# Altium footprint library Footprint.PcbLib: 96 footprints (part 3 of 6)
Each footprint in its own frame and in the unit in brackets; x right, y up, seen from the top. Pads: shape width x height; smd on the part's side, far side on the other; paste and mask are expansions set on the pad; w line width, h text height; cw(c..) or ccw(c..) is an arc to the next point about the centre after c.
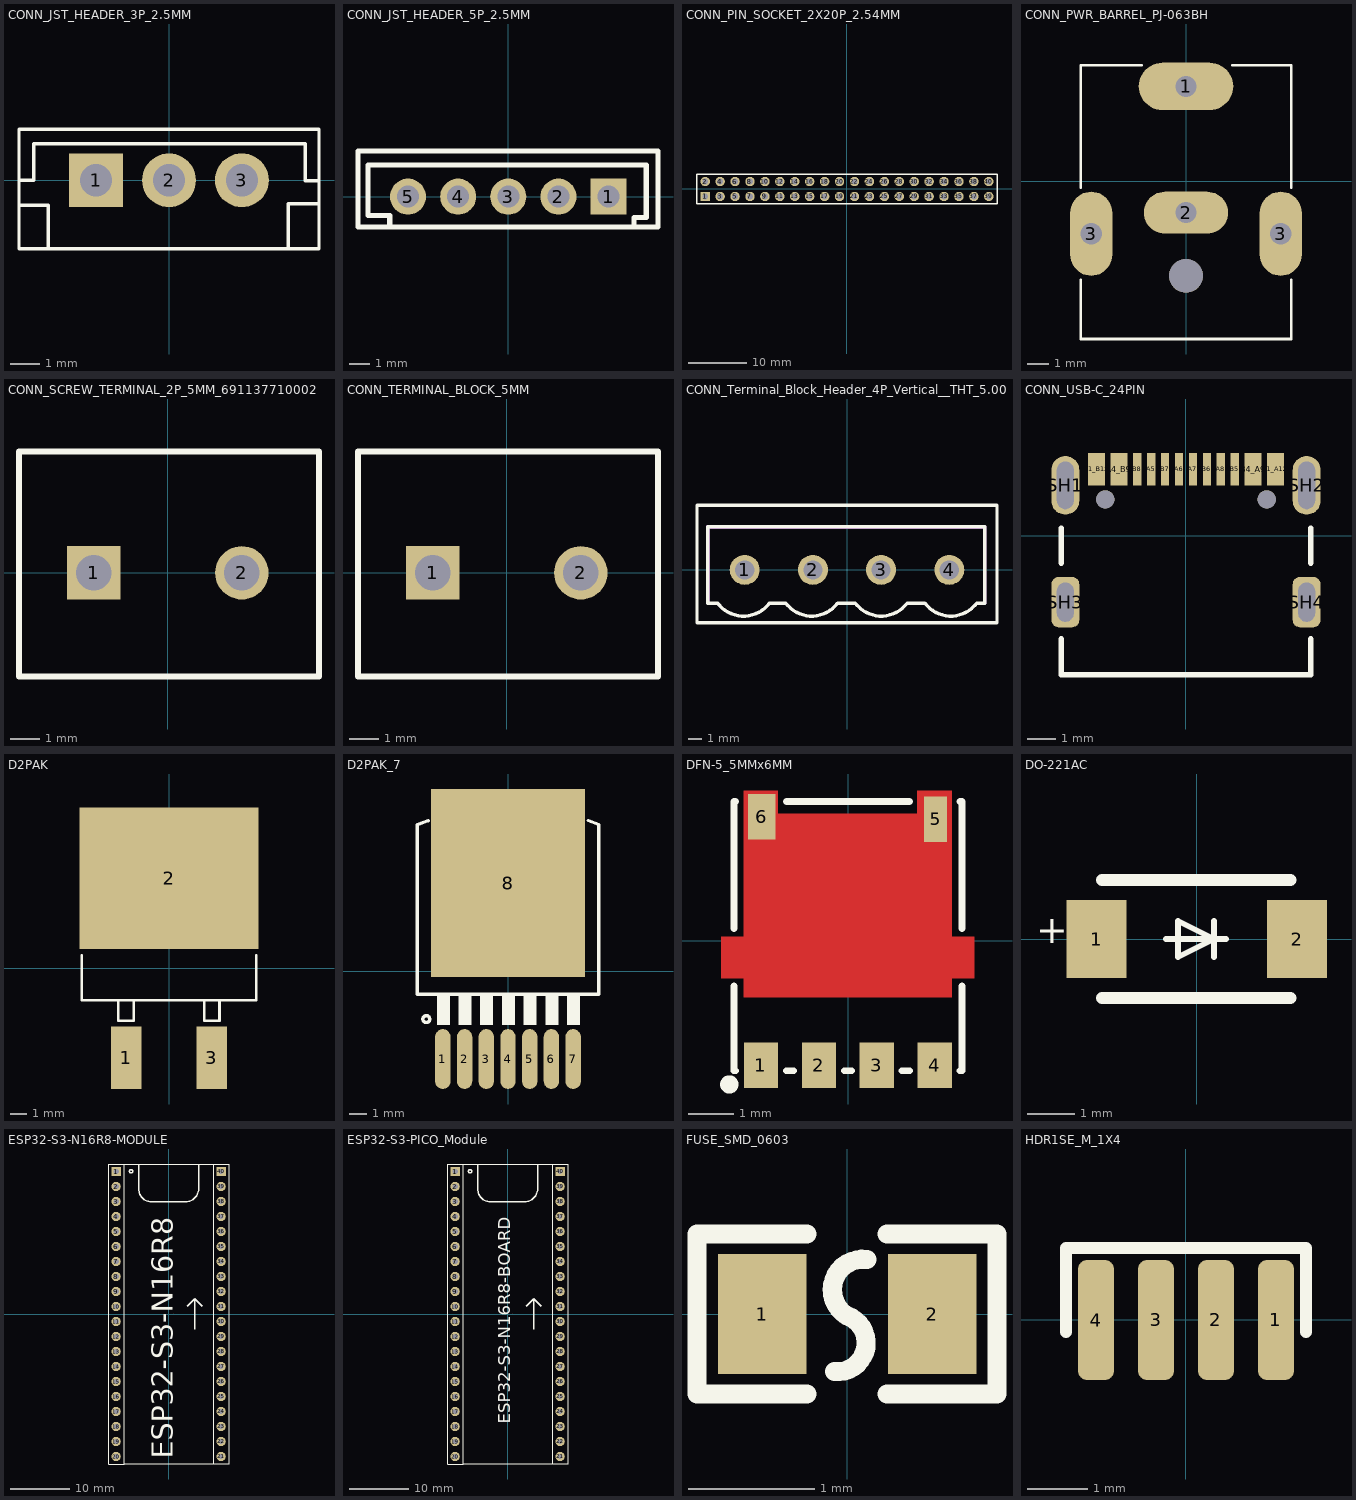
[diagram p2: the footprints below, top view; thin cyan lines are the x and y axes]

## CONN_JST_HEADER_3P_2.5MM [mm]
pads (3):
  rect 1.85x1.85 hole 1.1 paste+0 mask+0.051: 1(-2.5,0)
  round 1.85 hole 1.1 paste+0 mask+0.051: 2(0,0) 3(2.5,0)
Top Overlay:
  lines w0.12: -5.149,-0.851 -4.151,-0.851 -4.151,-2.349 ; -5.149,0 -4.649,0 -4.649,1.25 4.678,1.25 ; 4.099,-2.299 4.099,-0.8 5.1,-0.8 ; 4.678,1.232 4.678,-0.018 5.128,-0.018 ; -5.149,-2.349 5.148,-2.349 5.148,1.75 -5.149,1.75 -5.149,-2.349
3D body "JST-B3B-EH-A.STEP": height 6.1, standoff -3.1, extent -5,-2.2 5,1.6

## CONN_JST_HEADER_5P_2.5MM [mm]
pads (5):
  rect 1.8x1.8 hole 1.1 paste+0 mask+0.051: 1(5,0)
  round 1.8 hole 1.1 paste+0 mask+0.051: 2(2.5,0) 3(0,0) 4(-2.5,0) 5(-5,0)
Top Overlay:
  lines w0.254: -7.494,-1.524 -7.494,2.286 ; -7.466,-1.524 7.466,-1.524 ; -7.466,2.286 7.466,2.286 7.466,-1.524 ; -5.909,-1.463 -5.909,-0.94 -6.989,-0.94 -6.989,1.575 6.88,1.575 6.88,-1.039 6.267,-1.039 6.267,-1.397 ; 7.466,0 7.466,-1.524
3D body "JST-B5B-EH-A.STEP": height 6, standoff -3.2, extent -7.5,-1.6 7.5,2.2

## CONN_PIN_SOCKET_2X20P_2.54MM [mm]
pads (40):
  rect 1.6x1.6 hole 1 paste+0 mask+0.051: 1(-24.13,-1.27)
  round 1.6 hole 1 paste+0 mask+0.051: 2(-24.13,1.27) 3(-21.59,-1.27) 4(-21.59,1.27) 5(-19.05,-1.27) 6(-19.05,1.27) 7(-16.51,-1.27) 8(-16.51,1.27) 9(-13.97,-1.27) 10(-13.97,1.27) 11(-11.43,-1.27) 12(-11.43,1.27) 13(-8.89,-1.27) 14(-8.89,1.27) 15(-6.35,-1.27) 16(-6.35,1.27) 17(-3.81,-1.27) 18(-3.81,1.27) 19(-1.27,-1.27) 20(-1.27,1.27) 21(1.27,-1.27) 22(1.27,1.27) 23(3.81,-1.27) 24(3.81,1.27) 25(6.35,-1.27) 26(6.35,1.27) 27(8.89,-1.27) 28(8.89,1.27) 29(11.43,-1.27) 30(11.43,1.27) 31(13.97,-1.27) 32(13.97,1.27) 33(16.51,-1.27) 34(16.51,1.27) 35(19.05,-1.27) 36(19.05,1.27) 37(21.59,-1.27) 38(21.59,1.27) 39(24.13,-1.27) 40(24.13,1.27)
Top Overlay:
  lines w0.254: -25.527,-2.54 -25.527,2.54 25.527,2.54 25.527,-2.54 -25.527,-2.54
3D body "PinSocket_2x20_P2.54mm_Vertical.step": height 7, standoff -3.1, extent -25.4,-2.54 25.4,2.54

## CONN_PWR_BARREL_PJ-063BH [mm]
pads (5):
  oval 4.5x2.25 hole 1 square: 1(0,4.5)
  oval 4x2 hole 1 square: 2(0,-1.5)
  oval 2x4 hole 1 square: 3(-4.5,-2.5) 3(4.5,-2.5)
  round 1.6 hole 1.6 unplated: ""(0,-4.5)
Top Overlay:
  lines w0.127: -5,-4.7 -5,-7.5 5,-7.5 5,-4.7 ; -5,-0.3 -5,5.5 -2.1,5.5 ; 2.2,5.5 5,5.5 5,-0.3
3D body "CUI_DEVICES_PJ-063BH.step": height 9.5, standoff -2.5, extent -5.15,-7.493 5.15,5.507

## CONN_SCREW_TERMINAL_2P_5MM_691137710002 [mm]
pads (2):
  rect 1.8x1.8 / inner round 1.8 / far side rect 1.8x1.8 hole 1.2: 1(-2.5,0)
  round 1.8 hole 1.2: 2(2.5,0)
Top Overlay:
  lines w0.2: -5.015,-3.5 -5.015,4.1 5.1,4.1 5.1,-3.5 -5.015,-3.5
3D body "691137710002+%28rev1%29.stp": height 11.5, standoff -3.6, extent -4.949,-3.513 5.051,3.988

## CONN_TERMINAL_BLOCK_5MM [mm]
pads (2):
  rect 1.8x1.8 / inner round 1.8 / far side rect 1.8x1.8 hole 1.2: 1(-2.5,0)
  round 1.8 hole 1.2: 2(2.5,0)
Top Overlay:
  lines w0.2: -5.015,-3.5 5.1,-3.5 5.1,4.1 -5.015,4.1 -5.015,-3.5
3D body "691137710002.stp": height 3, standoff -12.1, extent -4.949,-3.512 5.051,3.988

## CONN_Terminal_Block_Header_4P_Vertical__THT_5.00mm_1755532 [mm]
pads (4):
  round 2.2 hole 1.4 paste+0 mask+0.05: 1(-7.5,0) 2(-2.5,0) 3(2.5,0) 4(7.5,0)
Top Overlay:
  lines w0.254: -0.69,-2.451 cw(c-2.59,-1.007) -4.489,-2.451 -5.689,-2.451 cw(c-7.59,-1.007) -9.489,-2.451 -10.199,-2.451 -10.199,3.149 10.101,3.15 10.101,-2.35 ; -0.589,-2.451 0.611,-2.451 ccw(c2.51,-1.007) 4.41,-2.451 ; 4.511,-2.451 5.711,-2.451 ; 5.711,-2.451 ccw(c7.61,-1.007) 9.51,-2.451 ; 9.511,-2.451 10.101,-2.451 ; 10.999,4.699 10.999,-3.899 -11,-3.899 -11,4.75 10.999,4.75
Mechanical 15:
  region: -10.327,-2.45 -10.327,3.15 -10.327,3.175 -10.308,3.222 -10.272,3.258 -10.225,3.277 -10.2,3.277 10.1,3.277 10.125,3.277 10.172,3.258 10.208,3.222 10.227,3.175 10.227,3.15 10.227,-2.45 10.227,-2.503 10.153,-2.577 10.047,-2.577 9.973,-2.503 9.973,-2.45 9.973,3.023 -10.073,3.023 -10.073,-2.45 -10.073,-2.503 -10.147,-2.577 -10.253,-2.577 -10.327,-2.503
3D body "1755532.STEP": height 12.25, standoff -3.8, extent -11,-3.828 11,4.742

## CONN_USB-C_24PIN [mm]
pads (18):
  rect 0.6x1.15 smd mask+0.04: A1_B12(-3.2,2.378) A4_B9(-2.4,2.378) B1_A12(3.2,2.378) B4_A9(2.4,2.378)
  rect 0.3x1.15 smd mask+0.04: A5(-1.25,2.378) A6(-0.25,2.378) A7(0.25,2.378) A8(1.25,2.378) B5(1.75,2.378) B6(0.75,2.378) B7(-0.75,2.378) B8(-1.75,2.378)
  oval 1x2.1 hole 0.6 slot 1.7 at 90 deg mask+0.04: SH1(-4.32,1.803) SH2(4.32,1.803)
  rrect50% 1x1.8 hole 0.6 slot 1.4 at 90 deg mask+0.04: SH3(-4.32,-2.377) SH4(4.32,-2.377)
  round 0.65 hole 0.65 unplated mask+0.04: ""(-2.89,1.303) ""(2.89,1.303)
Top Overlay:
  lines w0.2: -4.47,-3.697 -4.47,-4.977 4.47,-4.977 4.47,-3.697 ; -4.47,-0.977 -4.47,0.273 ; 4.47,-0.977 4.47,0.273
3D body "USB4105-GF-A.step": height 3.31, standoff -1.1, extent -4.495,-4.987 4.445,2.723

## D2PAK [mm]
pads (3):
  rect 1.8x3.7 smd paste+0 mask+0.051: 1(-2.54,-5.321) 3(2.54,-5.321)
  rect 10.608x8.4 smd paste+0 mask+0.051: 2(0,5.321)
Top Overlay:
  lines w0.152: -5.176,0.754 -5.176,-1.905 5.176,-1.905 5.176,0.754 ; -3,-1.905 -3,-3.12 -2.083,-3.12 -2.083,-1.905 ; 2.08,-1.905 2.08,-3.12 2.997,-3.12 2.997,-1.905
3D body "TO-263-2_L10.2-W8.7-H4.5-LS15.2-P2.54.step": height 4.5, standoff 0, extent -5.1,-5.914 5.1,9.114

## D2PAK_7 [mm]
pads (8):
  oval 0.9x3.5 smd: 1(-3.81,-5.15) 2(-2.54,-5.15) 3(-1.27,-5.15) 4(0,-5.15) 5(1.27,-5.15) 6(2.54,-5.15) 7(3.81,-5.15)
  rect 9x11 smd paste-5: 8(0,5.15)
Top Overlay:
  circle w0.2: c-4.779,-2.81 r0.2
  rectangle: 3.454,-3.15 4.216,-1.35
  rectangle: 2.184,-3.15 2.946,-1.35
  rectangle: 0.914,-3.15 1.676,-1.35
  rectangle: -0.356,-3.15 0.406,-1.35
  rectangle: -1.626,-3.15 -0.864,-1.35
  rectangle: -2.896,-3.15 -2.134,-1.35
  rectangle: -4.166,-3.15 -3.404,-1.35
  lines w0.2: -4.658,8.802 -5.3,8.559 -5.3,-1.35 5.3,-1.35 5.3,8.574 4.684,8.808
Top Designator:
  text ".Designator" at 2.917,2.161 h0.8
3D body "User Library-D2PAK-7.step": height 4.5, standoff 0, extent -5.2,-6.75 5.2,8.924

## DFN-5_5MMx6MM [mm]
pads (6):
  rect 0.75x1 smd paste+0 mask+0.051: 1(-1.914,-2.722) 2(-0.644,-2.722) 3(0.626,-2.722) 4(1.896,-2.722)
  rect 0.5x1 smd paste+0 mask+0.051: 5(1.914,2.671)
  rect 0.6x1 smd paste+0 mask+0.051: 6(-1.896,2.722)
Top Layer:
  region: -2.296,-1.24 -2.296,-0.815 -2.791,-0.815 -2.791,0.09 -2.296,0.09 -2.296,3.29 -1.546,3.29 -1.546,2.79 1.514,2.79 1.514,3.29 2.264,3.29 2.264,0.09 2.759,0.09 2.759,-0.815 2.264,-0.815 2.264,-1.24
Top Overlay:
  circle w0.2: c-2.609,-3.147 r0.1
  lines w0.152: -2.509,-0.992 -2.509,-2.847 -2.47,-2.847 ; -2.509,0.273 -2.509,3.053 -2.47,3.053 ; -1.359,-2.847 -1.2,-2.847 ; -1.359,3.053 1.34,3.053 ; -0.089,-2.847 0.07,-2.847 ; 1.181,-2.847 1.34,-2.847 ; 2.451,-2.847 2.49,-2.847 2.49,-0.992 ; 2.451,3.053 2.49,3.053 2.49,0.273
Top Paste:
  region: -2.296,-1.24 -2.296,-0.815 -2.791,-0.815 -2.791,0.09 -2.296,0.09 -2.296,3.29 -1.546,3.29 -1.546,2.79 1.514,2.79 1.514,3.29 2.264,3.29 2.264,0.09 2.759,0.09 2.759,-0.815 2.264,-0.815 2.264,-1.24
Top Solder:
  region: -2.327,-1.291 -2.327,-0.859 -2.835,-0.859 -2.835,0.131 -2.327,0.131 -2.327,3.332 -1.515,3.332 -1.515,2.824 1.483,2.824 1.483,3.332 2.295,3.332 2.295,0.131 2.778,0.131 2.778,-0.859 2.295,-0.859 2.295,-1.291
3D body "DFN-5_L6.1-W5.1-H1.0-P1.27.step": height 1.05, standoff 0, extent -2.575,-2.973 2.575,3.177

## DO-221AC [mil]
pads (2):
  rect 50x65 smd paste+0 mask+2: 1(-83.5,0) 2(83.5,0)
Top Overlay:
  lines w5: -25.5,0 24.5,0 ; 14.49,-15 14.49,0 ; 14.49,15 14.49,0 ; 14.49,0 -15.51,15 -15.51,0 -15.51,-15 14.49,0
  lines w10: -79.2,-49.2 78.19,-49.2 ; -79.2,49.2 78.19,49.2
  text "+" at -134,-11 h39.37
3D body "DO-221AC (SlimSMA).step": height 37.43, standoff 2, extent -104.33,-50.7 104.33,50.69

## ESP32-S3-N16R8-MODULE [mil]
pads (40):
  rect 62x62 hole 35 paste+0 mask+2: 1(-349.99,950) 40(349.99,950)
  round 62 hole 35 paste+0 mask+2: 2(-349.99,850) 3(-349.99,750) 4(-349.99,650) 5(-349.99,550) 6(-349.99,450) 7(-349.99,350) 8(-349.99,250) 9(-349.99,150) 10(-349.99,50) 11(-349.99,-50) 12(-349.99,-150) 13(-349.99,-250) 14(-349.99,-350) 15(-349.99,-450) 16(-349.99,-550) 17(-349.99,-650) 18(-349.99,-750) 19(-349.99,-850) 20(-349.99,-950) 21(349.99,-950) 22(349.99,-850) 23(349.99,-750) 24(349.99,-650) 25(349.99,-550) 26(349.99,-450) 27(349.99,-350) 28(349.99,-250) 29(349.99,-150) 30(349.99,-50) 31(349.99,50) 32(349.99,150) 33(349.99,250) 34(349.99,350) 35(349.99,450) 36(349.99,550) 37(349.99,650) 38(349.99,750) 39(349.99,850)
Top Overlay:
  circle w10: c-250.4,951.49 r11.05
  lines w7.99: -296,-1000 300,-1000 ; -296,1000 301,1000
  lines w8: -400,-1000 -400,1000 -295,1000 -295,-1000 -300,-1000 -400,-1000 ; 300,-1000 400,-1000 405,-1000 405,1000 300,1000 300,-1000
  lines w10: -200,999 -199.39,833.87 ccw(c-116.14,833.87) -175.01,775 -167.68,767.68 ccw(c-125.01,810.35) -125,750 -0.01,750 125,750 ccw(c125,810.35) 167.67,767.68 175,775 ccw(c114.64,835.35) 199.99,835.35 200,999 ; 125.19,50.08 175.27,100.16 ; 175.27,-100.16 175.27,100.16 ; 175.27,100.16 225.35,50.08 ; 225.35,50.08 225.35,50.08
  text "ESP32-S3-N16R8" at 73,-964 h236.22
Mechanical 15:
  lines w0.1: 34.99,4.99 35.01,5.01

## ESP32-S3-PICO_Module [mil]
pads (40):
  rect 62x62 hole 35 paste+0 mask+2: 1(-349.99,950) 40(349.99,950)
  round 62 hole 35 paste+0 mask+2: 2(-349.99,850) 3(-349.99,750) 4(-349.99,650) 5(-349.99,550) 6(-349.99,450) 7(-349.99,350) 8(-349.99,250) 9(-349.99,150) 10(-349.99,50) 11(-349.99,-50) 12(-349.99,-150) 13(-349.99,-250) 14(-349.99,-350) 15(-349.99,-450) 16(-349.99,-550) 17(-349.99,-650) 18(-349.99,-750) 19(-349.99,-850) 20(-349.99,-950) 21(349.99,-950) 22(349.99,-850) 23(349.99,-750) 24(349.99,-650) 25(349.99,-550) 26(349.99,-450) 27(349.99,-350) 28(349.99,-250) 29(349.99,-150) 30(349.99,-50) 31(349.99,50) 32(349.99,150) 33(349.99,250) 34(349.99,350) 35(349.99,450) 36(349.99,550) 37(349.99,650) 38(349.99,750) 39(349.99,850)
Top Overlay:
  circle w10: c-250.4,951.49 r11.05
  lines w7.99: -296,-1000 300,-1000 ; -296,1000 301,1000
  lines w8: -400,-1000 -300,-1000 -295,-1000 -295,1000 -400,1000 -400,-1000 ; 300,-1000 300,1000 405,1000 405,-1000 400,-1000 300,-1000
  lines w10: -200,999 -199.39,833.87 ccw(c-116.14,833.87) -175.01,775 -167.68,767.68 ccw(c-125.01,810.35) -125,750 -0.01,750 125,750 ccw(c125,810.35) 167.67,767.68 175,775 ccw(c114.64,835.35) 199.99,835.35 200,999 ; 125.19,50.08 175.27,100.16 ; 175.27,-100.16 175.27,100.16 ; 175.27,100.16 225.35,50.08 ; 225.35,50.08 225.35,50.08
  text "ESP32-S3-N16R8-BOARD" at 44.11,-731.91 h137.8
Mechanical 15:
  lines w0.1: 34.99,4.99 35.01,5.01

## FUSE_SMD_0603 [mm]
pads (2):
  rect 0.7x0.95 smd paste-100 mask+0.051: 1(-0.675,0) 2(0.675,0)
Top Overlay:
  lines w0.152: -1.192,0.635 -1.192,-0.635 -0.319,-0.635 ; -1.183,0.635 -0.319,0.635 ; -0.1,-0.457 ccw(c-0.079,-0.229) -0.003,-0.013 cw(c0.123,0.192) 0.154,0.432 ; 0.316,-0.635 1.188,-0.635 1.188,0.635 ; 0.316,0.635 1.179,0.635
3D body "fuse_silicon_0603L.step": height 0.45, standoff 0, extent -0.915,-0.52 0.886,0.52

## HDR1SE_M_1X4 [mm]
pads (4):
  rrect50% 0.6x2 smd mask+0.04: 1(1.5,0) 2(0.5,0) 3(-0.5,0) 4(-1.5,0)
Top Overlay:
  lines w0.2: -2,-0.2 -2,1.2 2,1.2 2,-0.2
